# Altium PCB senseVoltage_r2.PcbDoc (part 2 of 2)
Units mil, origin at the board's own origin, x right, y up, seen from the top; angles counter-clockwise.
Board outline 4100 x 1400 mil, 2 copper layers (Top Layer, Bottom Layer), stack 62 mil thick; 83 components, 46 nets, 184 pads, 26 vias.
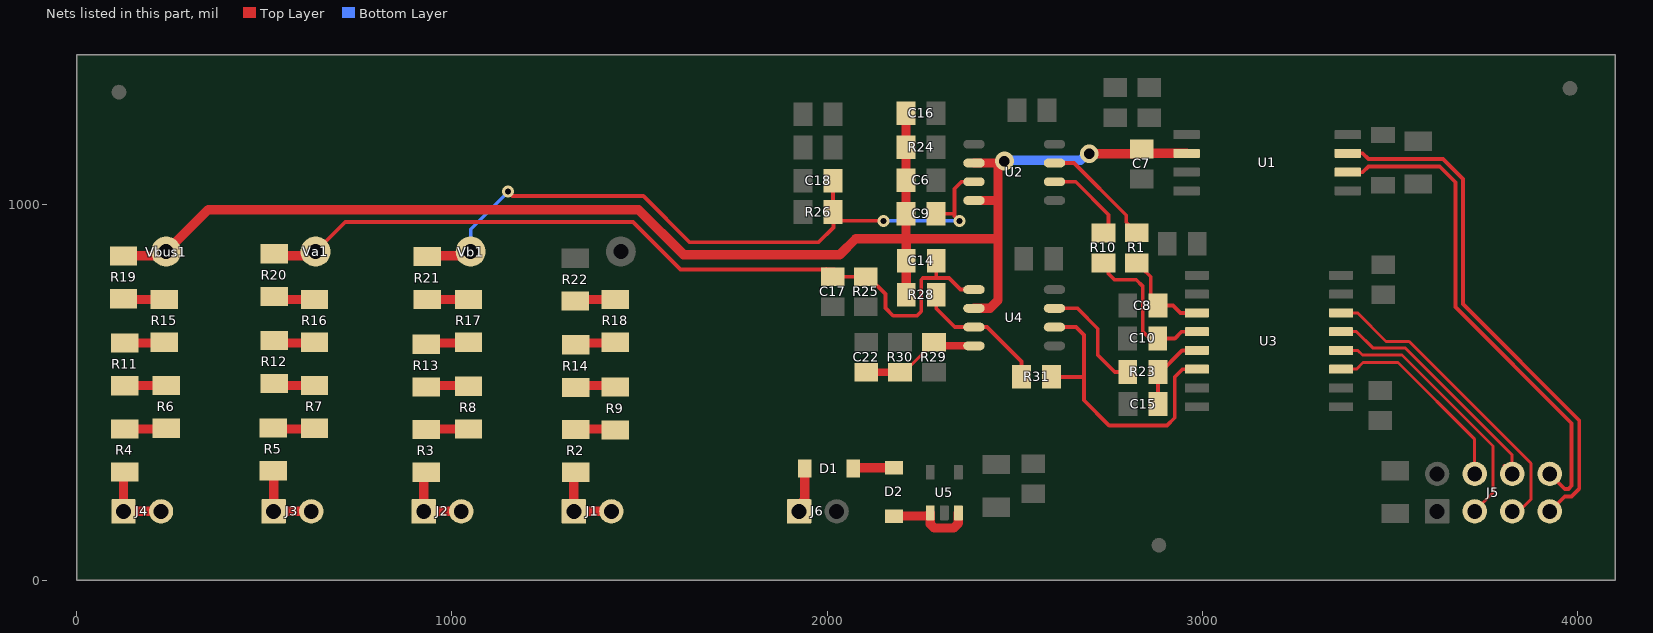
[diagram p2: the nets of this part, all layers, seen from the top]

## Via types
v1: diameter 50, hole 28, Top Layer to Bottom Layer, 18 vias
v2: diameter 32, hole 16, Top Layer to Bottom Layer, 4 vias
v3: diameter 40, hole 20, Top Layer to Bottom Layer, 4 vias

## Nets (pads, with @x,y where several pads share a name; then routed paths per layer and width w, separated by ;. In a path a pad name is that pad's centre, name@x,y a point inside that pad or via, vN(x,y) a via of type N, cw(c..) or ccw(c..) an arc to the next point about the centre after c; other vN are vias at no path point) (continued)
NetC6_2: C6.2 C7.1 C9.2 C14.2 C16.2 R19.1 R24.2 R28.2 U1.2 U2.2 U2.4 U4.2 Vbus1.1 | length 3994.9
  Top Layer w25: R19.1@125,863.73 227.33,863.73 Vbus1.1@238.6,875 254.2,890.6 350.44,986.84 1497.28,986.84 1616.99,867.12 2033.83,867.12 2075.88,909.17 2202.52,909.17 2209.86,916.52 ; C16.2@2209.86,1243.74 R24.2@2209.86,1153.35 C6.2@2209.86,1065.2 C9.2@2209.86,975.68 2209.86,935.72 2209.86,916.52 ; R28.2@2210.39,771.4 2210.39,909.17 ; U4.2@2390.81,723.92 2433.58,723.92 2455,745.34 2455,909.17 ; U2.4@2390.86,1011.18 2455,1011.18 ; U2.2@2390.86,1111.18 v1@2467.27,1111.18 ; v1@2455,1098.91 2455,1011.18 ; v1(2697.96,1135.92) 2837.26,1135.92 C7.1@2850,1148.66 ; C7.1@2837.85,1148.49 2838.01,1148.66 C7.1@2850,1148.66 ; U1.2@2957.4,1136.83 2861.83,1136.83 C7.1@2850,1148.66 ; 2209.86,916.52 2209.86,909.17 2210.39,909.17 ; 2209.86,916.52 2210.39,917.05 2210.39,909.17 ; 2210.39,909.17 2455,909.17 ; 2455,909.17 2455,1011.18
  Bottom Layer w25: v1(2472.26,1116.17) v1@2474.75,1118.66 ; v1@2494.75,1118.66 2674.88,1118.66 2692.14,1135.92 v1(2697.96,1135.92)
NetC8_1: C8.1 R1.2 U3.3 | length 248.4
  Top Layer w10: R1.2@2838.36,850 2838.36,831.67 2861.95,808.09 2861.95,750.41 C8.1@2880.95,731.4 2921.61,731.4 2941.19,711.82 U3.3@2985.04,711.82
NetC9_1: C9.1 C18.1 R21.1 R26.2 U2.3 Vb1.1 | length 1948.2
  Top Layer w10: v2(1150,1034.78) 1161.59,1023.19 1510.07,1023.19 1633.27,900 1976.95,900 2016.54,939.59 2016.54,979.59 2039.13,957 v2(2150,957) ; R26.2@2015.59,980.54 C18.1@2015.59,1063.84 ; C9.1@2289.86,975.68 2338.72,975.68 2338.99,975.95 ; v2(2352,957) 2338.99,970.01 2338.99,975.95 ; U2.3@2390.86,1061.18 2357.64,1061.18 2338.99,1042.53 2338.99,975.95
  Top Layer w25: R21.1@925,863.73 1027.33,863.73 Vb1.1@1054.2,890.6
  Bottom Layer w10: Vb1.1@1050,875 1050,934.78 v2(1150,1034.78) ; v2(2150,957) v2(2352,957)
NetC10_1: C10.1 R10.2 U3.4 | length 418.6
  Top Layer w10: R10.2@2749.67,850 2749.67,816 2765.67,800 2823.52,800 2840.36,783.16 2840.36,663 2859.68,643.68 C10.1@2880.36,643.68 2926.24,643.68 2944.38,661.82 U3.4@2985.04,661.82
NetC14_1: C14.1 C17.1 R20.1 R25.2 U4.1 Va1.1 | length 2208.6
  Top Layer w10: Va1.1@636.76,875 638.6,875 638.6,876.84 715.56,953.8 1482.75,953.8 1609.24,827.3 C17.1@1998.9,827.3 ; C17.1@1997.14,829.06 C17.1@1998.9,827.3 ; C17.1@2019.69,827.3 C17.1@1998.9,827.3 ; 2290,805 2290.39,805.39 C14.1@2290.39,850.42 C14.1@2290.39,855.84 ; U4.1@2390.81,773.92 2354.93,773.92 2324.35,804.5 2254.89,804.5 2250.39,800 2250.39,715.88 2238.91,704.41 2175.58,704.41 2155,724.98 2155,761.85 2108.65,808.2 R25.2@2103,808.2 2018,808.2 C17.1@1998.9,827.3
  Top Layer w25: R20.1@525,863.73 627.33,863.73 Va1.1@638.6,875
NetC15_1: C15.1 R23.2 U3.5 | length 236
  Top Layer w10: C15.1@2880.95,456.05 R23.2@2880.95,540.37 ; R23.2@2880.95,554.41 R23.2@2880.95,547.19 ; U3.5@2985.04,611.82 2945.58,611.82 R23.2@2880.95,547.19 ; R23.2@2880.95,540.37 R23.2@2880.95,547.19 ; R23.2@2880.95,540.37 R23.2@2880.95,547.19
NetC22_1: C22.1 R29.1 R30.2 U4.4 | length 311.1
  Top Layer w8: R30.2@2194.05,553.42 2204.44,553.42 R29.1@2284.44,633.42
  Top Layer w20: C22.1@2104.05,553.42 R30.2@2194.05,553.42 ; R29.1@2284.44,633.42 2293.94,623.92 U4.4@2378.05,623.92
NetD1_1: D1.1 J6.1 | length 141.6
  Top Layer w25: J6.1@1925,182.88 J6.1@1925,199.36 ; J6.1@1939.86,184.5 J6.1@1925,199.36 ; D1.1@1940.53,297 1940.53,214.89 J6.1@1925,199.36
NetD1_2: D1.2 D2.1 | length 104.5
  Top Layer w25: D1.2@2074.95,296.04 2078.38,299.47 D2.1@2178,299.47
NetD2_2: D2.2 U5.1 U5.3 | length 241.4
  Top Layer w25: D2.2@2178,170.53 2266.26,170.53 U5.1@2274.6,178.87 2274.6,149.4 2285.19,138.81 2336.81,138.81 2349.4,151.4 U5.3@2349.4,178.87
NetR1_1: R1.1 U2.7 | length 307.3
  Top Layer w10: U2.7@2605.42,1111.18 2657.19,1111.18 2796.55,971.82 2796.55,953.12 R1.1@2824.67,925
NetR2_1: R2.1 R9.2 | length 106.3
  Top Layer w25: R2.1@1328.57,402.32 1432.01,402.32 R9.2@1434,404.31
NetR3_1: R3.1 R8.2 | length 106.3
  Top Layer w25: R3.1@928.57,402.32 1032.01,402.32 R8.2@1034,404.31
NetR4_1: R4.1 R6.2 | length 106.3
  Top Layer w25: R4.1@128.57,402.32 232.01,402.32 R6.2@234,404.31
NetR5_1: R5.1 R7.2 | length 106.3
  Top Layer w25: R5.1@528.57,402.32 632.01,402.32 R7.2@634,404.31
NetR6_1: R6.1 R11.2 | length 83.1
  Top Layer w25: R11.2@150.89,518.48 R6.1@234,518.48
NetR7_1: R7.1 R12.2 | length 83.1
  Top Layer w25: R12.2@550.89,518.48 R7.1@634,518.48
NetR8_1: R8.1 R13.2 | length 83.1
  Top Layer w25: R13.2@950.89,518.48 R8.1@1034,518.48
NetR9_1: R9.1 R14.2 | length 83.1
  Top Layer w25: R14.2@1350.89,518.48 R9.1@1434,518.48
NetR10_1: R10.1 U2.6 | length 224.1
  Top Layer w10: U2.6@2605.42,1061.18 2662,1061.18 2749.67,973.51 R10.1@2749.67,930
NetR11_1: R11.1 R15.2 | length 106.5
  Top Layer w25: R11.1@128.57,631.67 151.87,631.67 152.09,631.45 R15.2@235,631.45
NetR12_1: R12.1 R16.2 | length 106.5
  Top Layer w25: R12.1@528.57,631.67 551.87,631.67 552.09,631.45 R16.2@635,631.45
NetR13_1: R13.1 R17.2 | length 106.5
  Top Layer w25: R13.1@928.57,631.67 951.87,631.67 952.09,631.45 R17.2@1035,631.45
NetR14_1: R14.1 R18.2 | length 106.5
  Top Layer w25: R14.1@1328.57,631.67 1351.87,631.67 1352.09,631.45 R18.2@1435,631.45
NetR15_1: R15.1 R19.2 | length 110.8
  Top Layer w25: R19.2@125,749.56 126.97,747.59 R15.1@234,747.59 R15.1@235,747.59
NetR16_1: R16.1 R20.2 | length 110.8
  Top Layer w25: R20.2@525,749.56 526.97,747.59 R16.1@634,747.59 R16.1@635,747.59
NetR17_1: R17.1 R21.2 | length 110.8
  Top Layer w25: R21.2@925,749.56 926.97,747.59 1034,747.59 R17.1@1035,747.59
NetR18_1: R18.1 R22.2 | length 110.8
  Top Layer w25: R22.2@1325,749.56 1326.97,747.59 1434,747.59 R18.1@1435,747.59
NetR23_1: R23.1 U4.7 | length 306.7
  Top Layer w10: U4.7@2605.37,723.92 2666.61,723.92 2720.97,669.56 2720.97,599.73 2766.29,554.41 R23.1@2800.95,554.41
NetR28_1: R28.1 R31.2 U4.3 | length 362.2
  Top Layer w10: R28.1@2290.39,771.4 R28.1@2290.39,760 2290.39,723.27 2339.74,673.92 U4.3@2378.05,673.92 ; U4.3@2390.81,673.92 2426.06,673.92 2517.79,582.19 R31.2@2517.79,541.24
NetR31_1: R31.1 U3.6 U4.6 | length 782.3
  Top Layer w10: U4.6@2605.37,673.92 2663.19,673.92 2684.26,652.84 2684.26,541.24 ; R31.1@2617.79,541.24 2684.26,541.24 ; U3.6@2985.04,561.82 2946.59,561.82 2925.9,541.13 2925.9,432.5 2905.38,411.98 2751.08,411.98 2684.26,478.8 2684.26,541.24
OVP: J5.4 U3.11 | length 548.1
  Top Layer w8: U3.11@3368.9,561.82 3409.89,561.82 3427.57,579.5 3520.6,579.5 3725,375.1 J5.4@3725,283.82 ; J5.4@3719.5,278.32 J5.4@3725,283.82 ; J5.4@3725,282.88 J5.4@3725,283.82
Vdc_N: J5.8 U1.6 | length 1336.3
  Top Layer w10: U1.6@3386.53,1086.83 3426.97,1086.83 3441.97,1101.83 3632.03,1101.83 3673.84,1060.03 3673.84,727.1 3983.33,417.61 3983.33,251.21 3975,242.88 3965,242.88 J5.8@3929.56,278.32 ; J5.8@3919.5,278.32 J5.8@3929.56,278.32 ; J5.8@3925,282.88 J5.8@3929.56,278.32
Vdc_P: J5.7 U1.7 | length 1398
  Top Layer w10: U1.7@3386.53,1136.83 3426.97,1136.83 3441.97,1121.83 3640.32,1121.83 3693.84,1068.31 3693.84,735.38 4003.33,425.89 4003.33,242.93 3983.28,222.88 3965,222.88 J5.7@3925,182.88 ; J5.7@3919.5,178.32 J5.7@3925,178.32
Vdcbus: J4.1 J4.2 R4.2 | length 206.7
  Top Layer w25: R4.2@128.57,288.14 125,284.57 J4.1@125,182.88 J4.2@225,182.88
VinvA: J5.5 U3.14 | length 833.4
  Top Layer w8: U3.14@3368.9,711.82 3412.62,711.82 3488.61,635.83 3550.37,635.83 3840.87,345.33 3840.87,344.99 3875,310.86 3875,215 3838.32,178.32 J5.5@3825,178.32
VinvB: J5.6 U3.13 | length 674
  Top Layer w8: U3.13@3368.9,661.82 3410.22,661.82 3453.3,618.75 3539.49,618.75 3825,333.24 J5.6@3825,282.88 J5.6@3802.75,305.13
VinvC: J5.3 U3.12 | length 711.9
  Top Layer w8: U3.12@3368.9,611.82 3413.75,611.82 3425.85,599.73 3531.25,599.73 3774,356.98 3774,232.82 J5.3@3719.5,178.32
VphaseA: J3.1 J3.2 R5.2 | length 206.7
  Top Layer w25: R5.2@528.57,288.14 525,284.57 J3.1@525,182.88 J3.2@625,182.88
VphaseB: J2.1 J2.2 R3.2 | length 206.7
  Top Layer w25: R3.2@928.57,288.14 925,284.57 J2.1@925,182.88 J2.2@1025,182.88
VphaseC: J1.1 J1.2 R2.2 | length 206.7
  Top Layer w25: R2.2@1328.57,288.14 1325,284.57 J1.1@1325,182.88 J1.2@1425,182.88
pads on no net: FID1.1 FID2.1 FID3.1 U3.7 U5.4

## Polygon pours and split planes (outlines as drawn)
HV_GND on Bottom Layer "BOTTOM_LAYER_HV_GND_P010" (solid, remove dead copper, pour order 10): 2884.39,1350.06 100.06,1350.06 50.72,1300.72 50.72,863.28 114,800 1749.24,800 1850,699.24 1850,100 1900,50 2900.08,50 3000,149.91 3000,1234.46
DGND on Bottom Layer "BOTTOM_LAYER_DGND_P012" (solid, remove dead copper, pour order 12): 4050,105 4050,1296.65 3996.65,1350 3426.72,1350 3380.41,1303.7 3380.41,120.22 3450.63,50 3995,50
3V3 on Top Layer "TOP_LAYER_3V3_P018" (solid, remove dead copper, pour order 18): 4050,107.88 4050,1295 3995,1350 3430,1350 3380.41,1300.41 3380.41,119.73 3450.15,50 3992.12,50
HV_3V3 on Top Layer "TOP_LAYER_HV_3V3_P016" (solid, remove dead copper, pour order 16): 1850,1299.54 1850,100 1900,50 2900.09,50 3000,149.91 3000,1233.16 2883.16,1350 1900,1350
no net on Top Layer "TOP_LAYER_NONET_P014" (solid, remove dead copper, pour order 14): 2285,335

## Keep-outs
Keep-Out Layer:
  text ".Layer_Name" at 577,-858.49 h60

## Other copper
Top Layer:
  text ".Layer_Name" at 577,-858.49 h60
Bottom Layer:
  text ".Layer_Name" at 577,-858.49 h60

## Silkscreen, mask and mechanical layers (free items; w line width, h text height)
Top Overlay:
  lines w8: 2037,669.56 2037,670 2048,681 2229.05,680.43 2248.05,699.43 ; 2238.05,699.43 2248.05,699.43 ; 2248.05,689.43 2248.05,699.43
  lines w25: 3175,44.88 3175,1375
  text "Voltage Sense" at 1189.12,1254.6 h80
  text "'.PRJ_Number'.PCB_Rev" at 1201.32,1169.6 h70
  text "Danger High Voltage" at 178.74,1050 h100
  text "HIGH VOLTAGE" at 3140,50 h55 r90
  text "LOW VOLTAGE" at 3250,50 h55 r90
  text ".Layer_Name" at 577,-858.49 h60
Bottom Overlay:
  lines w25: 3175,45 3175,1375.12
  text "Danger High Voltage" at 1690,1075 h100
  text "HIGH VOLTAGE" at 3140,900.12 h55 r90
  text "LOW VOLTAGE" at 3250,900.12 h55 r90
  text ".Layer_Name" at 577,-858.49 h60
Top Paste:
  text ".Layer_Name" at 577,-858.49 h60
Bottom Paste:
  text ".Layer_Name" at 577,-858.49 h60
Top Solder:
  text ".Layer_Name" at 577,-858.49 h60
  text ".Layer_Name" at 577,-858.49 h60
Bottom Solder:
  text ".Layer_Name" at 577,-858.49 h60
Drill Guide:
  text ".Layer_Name" at 577,-858.49 h60
M1 Board Outline:
  the board outline again, w10
  text ".Layer_Name" at 577,-858.49 h60
M2 Board Dimensions:
  rectangle: 0,-275 125,-150
  rectangle: 125,-400 500,-275
  lines w7: 0,-275 1000,-275 ; 125,-400 125,-150 ; 250,-400 250,-150 ; 500,-400 500,-150 ; 750,-400 750,-150 ; 0,-400 1000,-400 1000,-150 0,-150 0,-400
  text ".Layer_Name" at 577,-858.49 h60
M3 3D STEP Top:
  text ".Layer_Name" at 577,-858.49 h60
M4 3D STEP Bottom:
  text ".Layer_Name" at 577,-858.49 h60
M5 Assembly Top:
  lines w10: -292,-930.17 6308,-930.17 ; -292,-726.83 6310,-726.83 ; -292,-523.5 -292,-1133.5 3713,-1133.5 6310,-1133.5 6310,-523.5 -291.5,-523.5 -291.5,-1133.5 1284,-1133.5 ; 2173,-1133.5 2173,-523.5 ; 3440,-726.83 3440,-523.5 ; 4280,-726.83 4280,-523.5 ; 4902,-1140 4902,-937.17
  text "COMPONENTS MARKED 'DNP' SHOULD NOT BE POPULATED." at 1153.5,-318.5 h60
  text "ASSEMBLY VARIANT:" at 1153,-434 h60
  text ".VariantName" at 2189,-434 h60
  text "PCB VIEWED FROM TOP SIDE" at -228.5,-655.67 h60
  text "BOARD #:" at 2248,-655.67 h60
  text ".PRJ_Number" at 2793.5,-655.67 h60
  text "REV:" at 3638,-655.67 h60
  text ".PCB_Rev" at 3929.5,-655.67 h60
  text "SVN REV:" at 4476,-655.67 h60
  text ".VersionControl_RevNumber" at 4982,-655.67 h60
  text "TID #:" at 2248,-859 h60
  text ".TID" at 2793.5,-859 h60
  text "PLOT NAME =" at -228.5,-1064.34 h60
  text ".plot_File_Name" at 577,-1064.34 h60
  text "GENERATED    :" at 2250,-1064.34 h60
  text ".Print_Date" at 3119.5,-1064.34 h60
  text ".Print_Time" at 3848.5,-1064.34 h60
  text "TEXAS INSTRUMENTS" at 5113,-1064.34 h60
M6 Assembly Bottom:
  lines w10: -292.5,-727.33 6309.5,-727.33 ; -290.5,-930.67 6309.5,-930.67 ; 1115.5,-1140.5 1115.5,-937.67 ; 1737.5,-727.33 1737.5,-524 ; 2577.5,-727.33 2577.5,-524 ; 3844.5,-1134 3844.5,-524 ; 4733.5,-1134 6309,-1134 6309,-524 -292.5,-524 -292.5,-1134 2304.5,-1134 6309.5,-1134 6309.5,-524
  text "COMPONENTS MARKED 'DNP' SHOULD NOT BE POPULATED." at 6102,-318 h60
  text ".VariantName" at 5058,-434 h60
  text "ASSEMBLY VARIANT:" at 6097,-434 h60
  text ".VersionControl_RevNumber" at 1035.5,-656.17 h60
  text "SVN REV:" at 1541.5,-656.17 h60
  text ".PCB_Rev" at 2088,-656.17 h60
  text "REV:" at 2379.5,-656.17 h60
  text ".PRJ_Number" at 3224,-656.17 h60
  text "BOARD #:" at 3769.5,-656.17 h60
  text "PCB VIEWED FROM BOTTOM SIDE" at 6246,-656.17 h60
  text ".TID" at 3224,-859.5 h60
  text "TID #:" at 3769.5,-859.5 h60
  text "TEXAS INSTRUMENTS" at 904.5,-1064.84 h60
  text ".Print_Time" at 2169,-1064.84 h60
  text ".Print_Date" at 2898,-1064.84 h60
  text "GENERATED    :" at 3767.5,-1064.84 h60
  text ".plot_File_Name" at 5440.5,-1064.84 h60
  text "PLOT NAME =" at 6246,-1064.84 h60
M9 Title Sheet:
  drawing of 57 lines, arcs and shapes, not listed
  text "1" at 739.84,8036.5 h70
  text "2" at 3235.5,8036.5 h70
  text "3" at 5724.84,8036.5 h70
  text "4" at 8231.51,8036.5 h70
  text "5" at 10730.5,8036.5 h70
  text "6" at 13235.5,8036.5 h70
  text "A" at -416.5,6893.5 h70
  text "A" at 14383.5,6893.5 h70
  text "B" at -416.5,4513.5 h70
  text "B" at 14383.5,4513.5 h70
  text "C" at -416.5,2138.5 h70
  text "C" at 14383.5,2138.5 h70
  text "PROJECT TITLE:" at 11343.5,277.5 h45
  text ".PRJ_Title" at 11393.5,144.17 h70
  text "DESIGNED FOR:" at 11343.5,-23.5 h45
  text ".PRJ_Customer" at 11393.5,-163.5 h70
  text "D" at -416.5,-231.5 h70
  text "D" at 14383.5,-231.5 h70
  text "FILE NAME:" at 11343.5,-323.5 h45
  text ".PCB_File_Name_No_Path" at 11393.5,-443.5 h70
  text "Texas Instruments (TI) and/or its licensors do not warrant the accuracy or completeness of this specification" at 6374,-605.34 h45
  text "ENGINEER:" at 11343.5,-613.5 h45
  text "LAYOUT BY:" at 12848.5,-613.5 h45
  text "or any information contained therein. TI and/or its licensors do not warrant that this design will meet" at 6329.01,-718 h45
  text ".PRJ_Engineer" at 11393.5,-768.49 h70
  text ".PCB_Layout" at 12899,-768.49 h70
  text "the specifications, will be suitable for your application or fit for any particular purpose, or will operate in" at 6329.01,-830.67 h45
  text ".Layer_Name" at 577,-858.49 h60
  text "ALTIUM DESIGNER VERSION:" at 12848.5,-923.5 h45
  text "an implementation. TI and/or its licensors do not warrant that the design is production worthy. You should" at 6329.01,-943.33 h45
  text "completely validate and test your design implementation to confirm the system functionality for your application." at 6374,-1056 h45
  text ".print_Scale" at 11393.5,-1056.83 h70
  text ".Application_BuildNumber" at 12899,-1056.83 h70
  text "1" at 739.84,-1263.5 h70
  text "2" at 3235.5,-1263.5 h70
  text "3" at 5724.84,-1263.5 h70
  text "4" at 8231.51,-1263.5 h70
  text "5" at 10730.5,-1263.5 h70
  text "6" at 13235.5,-1263.5 h70
M10 Fab Notes:
  drawing of 189 lines, arcs and shapes, not listed
  text "DESIGN INFORMATION" at 12382.02,6356.17 h60
  text "MIN. TRACK WIDTH:" at 11737.46,6224.05 h60
  text "8" at 12833.7,6224.05 h60
  text "MIL" at 12988.46,6224.05 h60
  text "MIN. CLEARANCE:" at 11737.46,6099.92 h60
  text "0.2" at 12773.7,6099.93 h60
  text "mm" at 12988.46,6099.92 h60
  text "MIN. VIA PAD SIZE:" at 11737.46,5975.8 h60
  text "24" at 12803.71,5975.8 h60
  text "MIL" at 12988.46,5975.8 h60
  text "0.05mm (2MIL)" at 12432.46,5845.9 h60
  text "MINIMUM ANNULAR RING" at 11408.23,5837.67 h60
  text "EXTERNAL" at 13140.46,5837.67 h60
  text "PER" at 11608.23,5727.55 h60
  text "IPC-D-275 CLASS 2 LEVEL C" at 11828.23,5727.54 h60
  text "MIL, HOLES" at 13316.46,5627.07 h60
  text "+/-" at 12924,5618.48 h60
  text "+/-" at 13778,5618.48 h60
  text "REGISTRATION TOLERANCES:" at 11408.23,5617.42 h60
  text "METAL" at 12608,5617.42 h60
  text "5" at 13184.2,5617.42 h60
  text "3" at 14017.2,5617.42 h60
  text "MIL" at 14133.46,5617.42 h60
  text "HOLE SIZE TOLERANCE (UNLESS OTHERWISE SPECIFIED):" at 11408.23,5519.1 h60
  text "+/-" at 13778,5516.23 h60
  text "3" at 14017.2,5515.17 h60
  text "MIL" at 14133.46,5515.17 h60
  text "MATERIAL:" at 11333.46,5377.52 h60
  text "FR-4 High Tg" at 12319.9,5249 h60
  text "X" at 12175.46,5241.01 h60
  text "FR-408" at 11754.46,5236.49 h60
  text "OTHER" at 13242.46,5236.49 h60
  text "62 MIL (1.6mm) +/-10%" at 12074.56,5093.46 h60
  text "X" at 11954.46,5091.01 h60
  text "THICKNESS:" at 11408.23,5085.24 h60
  text "OTHER" at 13359.46,5085.24 h60
  text "TOLERANCE:" at 11408.23,4946.92 h60
  text "X" at 12256.46,4946.92 h60
  text "ANSI IPC-6012 TYPE 3 CLASS 2" at 12434.48,4946.92 h60
  text "OTHER +/-" at 12434.46,4802.73 h60
  text "BOW & TWIST:" at 11408.23,4657.54 h60
  text "X" at 12256.46,4657.54 h60
  text "ANSI IPC-6012 TYPE 3 CLASS 2" at 12434.48,4657.54 h60
  text "OTHER +/-" at 12434.46,4510.85 h60
  text "DRILLING:" at 11333.46,4380.23 h60
  text "NC_DRILL FILES" at 13094.46,4275.04 h60
  text "REFERENCE:" at 11408.23,4271.1 h60
  text "X" at 12065.46,4271.01 h60
  text "AS SHOWN" at 12243.46,4271.1 h60
  text "X" at 12966.46,4271.1 h60
  text "OTHER" at 13392.46,4128.85 h60
  text "PTH COPPER THICKNESS:" at 11407.91,4125.32 h60
  text "X" at 12547.14,4125.32 h60
  text "20-30 um" at 12675.14,4125.32 h60
  text "BOARD FINISH:" at 11333.46,3977.73 h60
  text "SILKSCREEN:" at 11488.68,3867.6 h60
  text "X" at 12446.46,3867.6 h60
  text "TOP" at 12563.46,3867.6 h60
  text "X" at 12956.46,3867.6 h60
  text "BOTTOM" at 13074.46,3867.6 h60
  text "SILKSCREEN COLOR:" at 11488.68,3712.41 h60
  text "X" at 12445.46,3712.41 h60
  text "WHITE" at 12563.46,3712.41 h60
  text "OTHER" at 13074.46,3712.41 h60
  text "X" at 12576.46,3568.96 h60
  text "GREEN" at 12694.46,3568.96 h60
  text "OTHER" at 13312.46,3568.96 h60
  text "SOLDER RESIST COLOR:" at 11488.68,3562.1 h60
  text "X" at 12576.46,3414.71 h60
  text "MATTE" at 12694.46,3414.71 h60
  text "SEMI-GLOSS" at 13312,3414.07 h60
  text "IMMERSION GOLD (ENIG)" at 12394.46,3241.94 h60
  text "ENEPIG" at 13732,3234.72 h60
  text "SURFACE FINISH:" at 11333.46,3233.72 h60
  text "X" at 12216.46,3233.72 h60
  text "IMM. TIN/SILVER OR EQUIV" at 11663,3096.4 h60
  text "OTHER" at 13094.46,3092.47 h60
  text "ARRAY/PANEL:" at 11333.46,2937.09 h60
  text "CUT AND TRIM PER M1 BOARD OUTLINE" at 12394.46,2928.87 h60
  text "N.C. ROUTE" at 12394.46,2792.9 h60
  text "X" at 13082.46,2792.9 h60
  text "V. SCORE" at 13260.46,2792.9 h60
  text "CERTIFICATION:" at 11333.46,2663.77 h60
  text "MATERIALS AND WORKMANSHIP FOR ALL PCBS" at 12058.46,2663.77 h60
  text "TO MEET OR EXCEED THE REQUIREMENTS OF:" at 12058.46,2569.71 h60
  text "X" at 11695.97,2441.08 h60
  text "ANSI IPC-A-600F CLASS ->" at 11823.96,2441.08 h60
  text "X" at 13471.97,2441.08 h60
  text "2" at 13581.96,2441.08 h60
  text "1" at 13266.96,2439.58 h60
  text "3" at 13935.96,2439.58 h60
  text "X" at 12507.97,2293.39 h60
  text "RoHS" at 12635.96,2293.39 h60
  text "OTHER" at 13280.36,2293.39 h60
  text "PER ORDER" at 13677.42,2293.39 h60
  text "ALL BOARDS MUST MEET OR EXCEED UL94-V0 REQUIREMENTS." at 11361,2139.57 h60
  text "PCB MUST BEAR THE UL94V-0 UL REGISTERED MATERIAL ID NUMBER" at 11361,2023.5 h60
  text "ADDITIONAL REQUIREMENTS:" at 11333.46,1854.08 h60
  text "MICROSECTION:" at 11408.23,1746.95 h60
  text "YES" at 12313.96,1746.95 h60
  text "REQUIRED" at 13175.46,1602.62 h60
  text "BARE BOARD ELEC. TEST:" at 11408.23,1599.76 h60
  text "NONE" at 12713.96,1599.76 h60
  text "X" at 13057.46,1599.76 h60
  text "PER ORDER" at 13767.46,1599.76 h60
  text "XX MIL VIAS REQUIRE NON-CONDUCTIVE FILL AND PLANARIZE" at 11576.38,1394.82 h59
  text "XX MIL VIAS REQUIRE CONDUCTIVE FILL AND PLANARIZE" at 11584.38,1290.84 h60
  text "OUTER XX MIL TRACES REQUIRE 50 OHM SINGLE-ENDED IMPEDANCE" at 11583.39,1127.46 h58
  text "LAYER 2 & 3 (INNER LAYERS) XX MIL WIDE, XX MIL SPACE / TRACES REQUIRE 100 OHM DIFFERENTIAL IMPEDANCE" at 11575.39,891.74 h60
  text ".Layer_Name" at 577,-858.49 h60
M11 Gerber Information:
  lines w10: -292,-930.17 6308,-930.17 ; -292,-726.83 6310,-726.83 ; -292,-523.5 -292,-1133.5 3713,-1133.5 6310,-1133.5 6310,-523.5 -291.5,-523.5 -291.5,-1133.5 1284,-1133.5 ; 2173,-1133.5 2173,-523.5 ; 3440,-726.83 3440,-523.5 ; 4280,-726.83 4280,-523.5 ; 4902,-1140 4902,-937.17
  text "ALL ARTWORK VIEWED FROM TOP SIDE" at -228.5,-655.67 h60
  text "BOARD #:" at 2248,-655.67 h60
  text ".PRJ_Number" at 2793.5,-655.67 h60
  text "REV:" at 3638,-655.67 h60
  text ".PCB_Rev" at 3929.5,-655.67 h60
  text "SVN REV:" at 4476,-655.67 h60
  text ".VersionControl_RevNumber" at 4982,-655.67 h60
  text "LAYER NAME =" at -228.5,-858.49 h60
  text "TID #:" at 2248,-859 h60
  text ".TID" at 2793.5,-859 h60
  text "PLOT NAME =" at -228.5,-1064.34 h60
  text ".plot_File_Name" at 577,-1064.34 h60
  text "GENERATED    :" at 2250,-1064.34 h60
  text ".Print_Date" at 3119.5,-1064.34 h60
  text ".Print_Time" at 3848.5,-1064.34 h60
  text "TEXAS INSTRUMENTS" at 5113,-1064.34 h60
M12 Stackup:
  drawing of 191 lines, arcs and shapes, not listed
  text "Layer" at 9811.59,7154.94 h60
  text "Name" at 10221.51,7154.94 h60
  text "Material" at 11151.25,7154.94 h60
  text "Thickness" at 12011.02,7154.94 h60
  text "Constant" at 12660.85,7154.94 h60
  text "Board Layer Stack" at 13230.71,7154.94 h60
  text "1" at 9811.59,7034.94 h60
  text "Top Overlay" at 10221.51,7034.94 h60
  text "2" at 9811.59,6914.94 h60
  text "Top Solder" at 10221.51,6914.94 h60
  text "Solder Resist" at 11151.25,6914.94 h60
  text "0.40mil" at 12011.02,6914.94 h60
  text "3.5" at 12660.85,6914.94 h60
  text "3" at 9811.59,6794.94 h60
  text "Top Layer" at 10221.51,6794.94 h60
  text "Copper" at 11151.25,6794.94 h60
  text "1.40mil" at 12011.02,6794.94 h60
  text "4" at 9811.59,6674.94 h60
  text "Dielectric1" at 10221.51,6674.94 h60
  text "FR-4" at 11151.25,6674.94 h60
  text "59.20mil" at 12011.02,6674.94 h60
  text "4.8" at 12660.85,6674.94 h60
  text "5" at 9811.59,6554.94 h60
  text "Bottom Layer" at 10221.51,6554.94 h60
  text "Copper" at 11151.25,6554.94 h60
  text "1.40mil" at 12011.02,6554.94 h60
  text "6" at 9811.59,6434.94 h60
  text "Bottom Solder" at 10221.51,6434.94 h60
  text "Solder Resist" at 11151.25,6434.94 h60
  text "0.40mil" at 12011.02,6434.94 h60
  text "3.5" at 12660.85,6434.94 h60
  text "7" at 9811.59,6314.94 h60
  text "Bottom Overlay" at 10221.51,6314.94 h60
  text ".Layer_Name" at 577,-858.49 h60
M13 Component Bodies Top:
  text ".Layer_Name" at 577,-858.49 h60
M14 Component Bodies Bottom:
  text ".Layer_Name" at 577,-858.49 h60
M15 Courtyards Top:
  text ".Layer_Name" at 577,-858.49 h60
M16 Courtyards Bottom:
  text ".Layer_Name" at 577,-858.49 h60
Drill Drawing:
  circle w10: c5858.13,4392.88 r27.63
  lines w10: 5830.51,4116.61 5885.76,4116.61 5885.76,4171.86 5830.51,4171.86 5830.51,4116.61 ; 5830.51,4240.93 5830.51,4254.74 5844.32,4268.56 5830.51,4282.37 5830.51,4296.18 5844.32,4296.18 5858.13,4282.37 5871.95,4296.18 5885.76,4296.18 5885.76,4282.37 5871.95,4268.56 5885.76,4254.74 5885.76,4240.93 5871.95,4240.93 5858.13,4254.74 5844.32,4240.93 5830.51,4240.93 ; 5830.51,4503.38 5844.32,4503.38 5858.13,4489.57 5871.95,4503.38 5885.76,4503.38 5871.95,4517.2 5885.76,4531.01 5871.95,4531.01 5858.13,4544.82 5844.32,4531.01 5830.51,4531.01 5844.32,4517.2 5830.51,4503.38 ; 5830.51,4613.89 5858.13,4627.7 5885.76,4613.89 5871.95,4641.52 5885.76,4669.14 5858.13,4655.33 5830.51,4669.14 5844.32,4641.52 5830.51,4613.89
  lines w12: 5780.42,4079.31 9011.9,4079.31 ; 5780.42,4700.91 9011.9,4700.91 ; 6118.28,3954.99 6118.28,4825.23 ; 6450.28,3954.99 6450.28,4825.23 ; 7086.84,3954.99 7086.84,4825.23 ; 7345.98,3954.99 7345.98,4825.23 ; 7721.14,3954.99 7721.14,4825.23 ; 8445.47,3954.99 8445.47,4825.23 ; 5780.42,3954.99 9011.9,3954.99 9011.9,4825.23 5780.42,4825.23 5780.42,3954.99
  text "Symbol" at 5855.01,4738.21 h72
  text "Quantity" at 6155.57,4738.21 h72
  text "Finished Hole Size" at 6487.57,4738.21 h72
  text "Plated" at 7124.14,4738.21 h72
  text "Hole Type" at 7383.28,4738.21 h72
  text "Drill Layer Pair" at 7758.44,4738.21 h72
  text "Hole Tolerance" at 8482.77,4738.21 h72
  text "4" at 6155.57,4613.89 h60
  text "16.00mil (0.406mm)" at 6487.57,4613.89 h60
  text "PTH" at 7124.14,4613.89 h60
  text "Round" at 7383.28,4613.89 h60
  text "Top Layer - Bottom Layer" at 7758.44,4613.89 h60
  text "4" at 6155.57,4489.57 h60
  text "20.00mil (0.508mm)" at 6487.57,4489.57 h60
  text "PTH" at 7124.14,4489.57 h60
  text "Round" at 7383.28,4489.57 h60
  text "Top Layer - Bottom Layer" at 7758.44,4489.57 h60
  text "18" at 6155.57,4365.25 h60
  text "28.00mil (0.711mm)" at 6487.57,4365.25 h60
  text "PTH" at 7124.14,4365.25 h60
  text "Round" at 7383.28,4365.25 h60
  text "Top Layer - Bottom Layer" at 7758.44,4365.25 h60
  text "18" at 6155.57,4240.93 h60
  text "39.37mil (1.000mm)" at 6487.57,4240.93 h60
  text "PTH" at 7124.14,4240.93 h60
  text "Round" at 7383.28,4240.93 h60
  text "Top Layer - Bottom Layer" at 7758.44,4240.93 h60
  text "4" at 6155.57,4116.61 h60
  text "40.00mil (1.016mm)" at 6487.57,4116.61 h60
  text "PTH" at 7124.14,4116.61 h60
  text "Round" at 7383.28,4116.61 h60
  text "Top Layer - Bottom Layer" at 7758.44,4116.61 h60
  text "48 Total" at 6155.57,3992.29 h60
  text ".Layer_Name" at 577,-858.49 h60
M17 Embedded Cavity:
  text ".Layer_Name" at 577,-858.49 h60
M18 Embedded Assembly:
  text ".Layer_Name" at 577,-858.49 h60
M19 Embedded Keepout:
  text ".Layer_Name" at 577,-858.49 h60

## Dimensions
0,0 to 0,1400 on M2 Board Dimensions
0,0 to 4100,0 on M2 Board Dimensions
0,-400 to 1000,-400 on M2 Board Dimensions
